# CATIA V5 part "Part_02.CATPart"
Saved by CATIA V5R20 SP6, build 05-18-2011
Part number: Part_02
Bounding box of the stored display mesh (mm): x -12.5 to 2.5, y -44 to 6, z -6 to 12
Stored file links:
  E:\#01 CATIA Lecture Materials\#16 3D Print Test\3D Print Test\17th Test\Part_02.CATPart
  E:\#01 CATIA Lecture Materials\#16 3D Print Test\3D Print Test\2nd Test\3D Print Test_02.CATProduct
  E:\#01 CATIA Lecture Materials\#16 3D Print Test\3D Print Test\17th Test\Part_01.CATPart
  E:\#01 CATIA Lecture Materials\#16 3D Print Test\3D Print Test\15th Test\3D Print Test_15.CATProduct
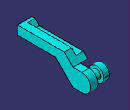
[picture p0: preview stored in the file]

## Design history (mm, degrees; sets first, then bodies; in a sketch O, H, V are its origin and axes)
Set1 "Reference Data"
  Point1 "Center Point": (0, 0, 0)
Body1 (main body)
  Sketch1 on yz-plane, origin (0, 0, 0), H (0, -1, 0), V (0, 0, 1)
    arc A1 centre (0, 0) radius 6 from (0, 6) to (0, -6) ccw
    point P1 (0, 6)
    line L1 (0, 6) -> (18, 6)
    line L2 (18, 6) -> (6, -6)
    point P3 (6, -6)
    line L3 (6, -6) -> (0, -6)
    distance L1 L3 = 12
    distance V P3 = 6
    angle L2 L1 = 135
    coincidence: P1 V
    tangency: L1 A1, L3 A1
    horizontal: L3 H, L1 H
  Pad1: profile Sketch1, direction (1, 0, 0), length 2.5, mirrored extent
  Sketch2 on face of Pad2, origin (-2.5, 0, 0), H (0, -1, 0), V (0, 0, 1)
    circle A1 centre (0, 0) radius 3
    radius A1 = 3
  Pad2: profile Sketch2, direction (-1, 0, 0), length 5
  Sketch3 on face of Pad3, origin (-7.5, 0, 0), H (0, -1, 0), V (0, 0, 1)
    circle A1 centre (0, 0) radius 5
    radius A1 = 5
  Pad3: profile Sketch3, direction (-1, 0, 0), length 5
  Sketch4 on yz-plane, origin (0, 0, 0), H (0, -1, 0), V (0, 0, 1)
    point P1 (6, 6)
    line L1 (6, 6) -> (44, 6)
    line L2 (44, 6) -> (44, 12)
    line L3 (44, 12) -> (12, 12)
    line L4 (12, 12) -> (6, 6)
    reference projected line E1 (0, -6) -> (6, -6) from edge [face of Pad1 from Sketch1.L3 | start face of Pad1]
    angle L4 H = 135
    distance V P1 = 6
    distance L1 L3 = 6
    distance V L2 = 44
    distance E1 L1 = 12
    horizontal: L1 H, L3 H
    vertical: L2 V
  Pad4: profile Sketch4, direction (-1, 0, 0), length 7.5, opposite side length 2.5
  Sketch5 on yz-plane, origin (0, 0, 0), H (0, -1, 0), V (0, 0, 1)
    line L1 (9, 9) -> (39, 9)
    point P2 (39, 9)
    line L2 (39, 9) -> (42, 12)
    point P3 (42, 12)
    line L3 (42, 12) -> (12, 12)
    line L4 (12, 12) -> (9, 9)
    reference projected line E1 (12, 12) -> (6, 6) from edge [face of Pad4 from Sketch4.L4 | end face of Pad4]
    reference projected line E2 (44, 12) -> (12, 12) from edge [face of Pad4 from Sketch4.L3 | end face of Pad4]
    reference projected line E3 (44, 6) -> (44, 12) from edge [face of Pad4 from Sketch4.L2 | end face of Pad4]
    distance L3 L1 = 3
    distance E3 P3 = 2
    distance P3 P2 H = 3
    horizontal: L1 H, L3 H
    coincidence: L4 E1, L3 E2
  Pocket1: profile Sketch5, direction (-1, 0, 0), through (limit type 6), opposite side length -2.5
  Fillet1: radius 1, on edge [face of Pad3 from Sketch3.A1 | end face of Pad3]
